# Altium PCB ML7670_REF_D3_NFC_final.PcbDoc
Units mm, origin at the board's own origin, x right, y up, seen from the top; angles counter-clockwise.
Board outline 50 x 7.2 mm, 4 copper layers (Top Layer, Inner Layer 1, Inner Layer 2, Bottom Layer), stack 0.195 mm thick; 35 components, 21 nets, 103 pads, 131 vias.
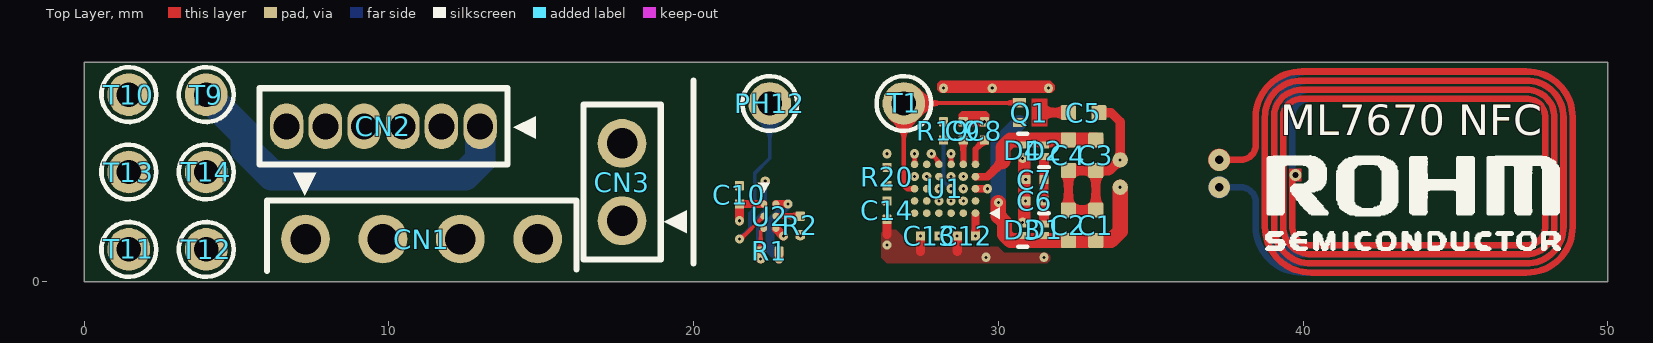
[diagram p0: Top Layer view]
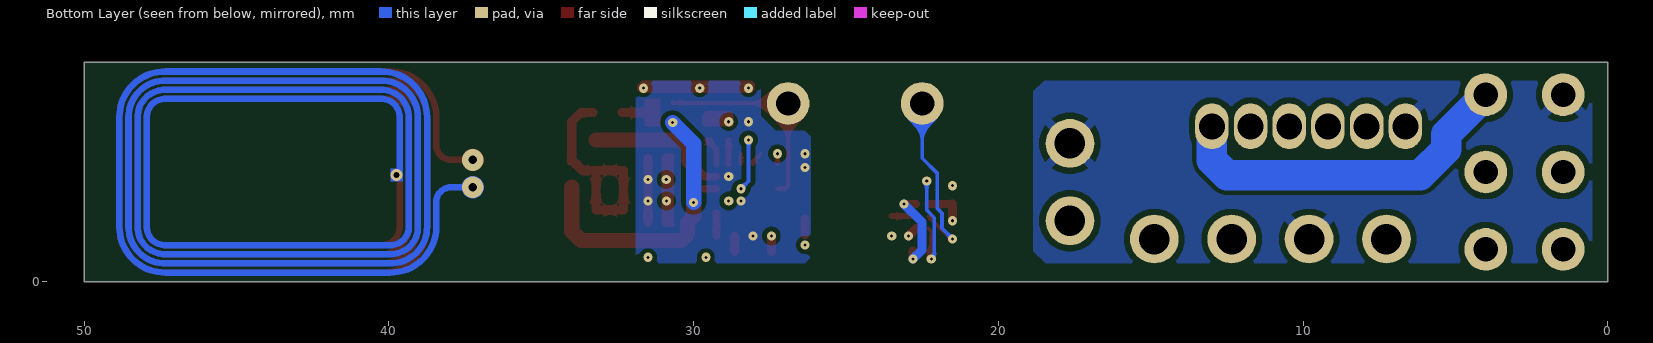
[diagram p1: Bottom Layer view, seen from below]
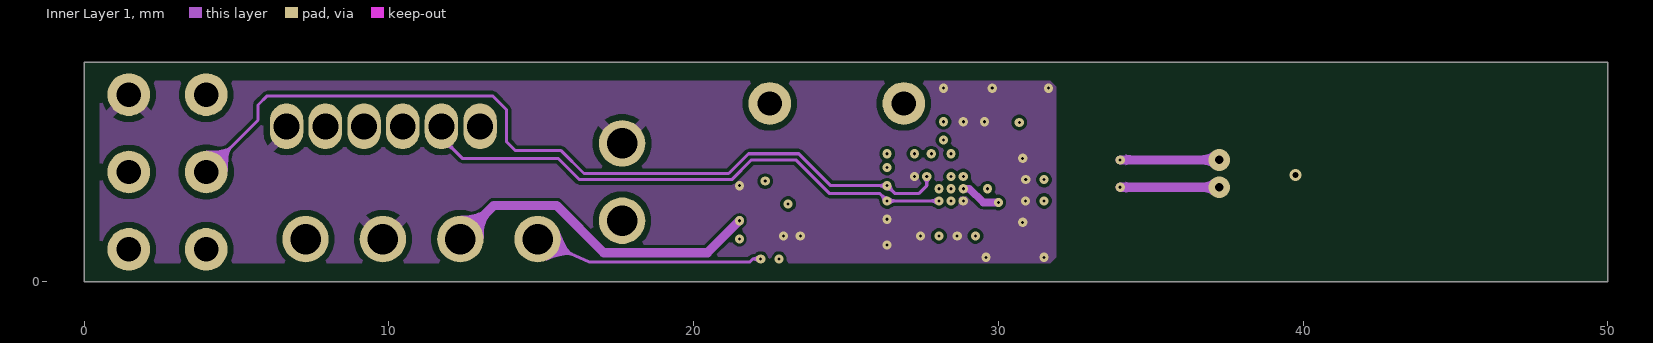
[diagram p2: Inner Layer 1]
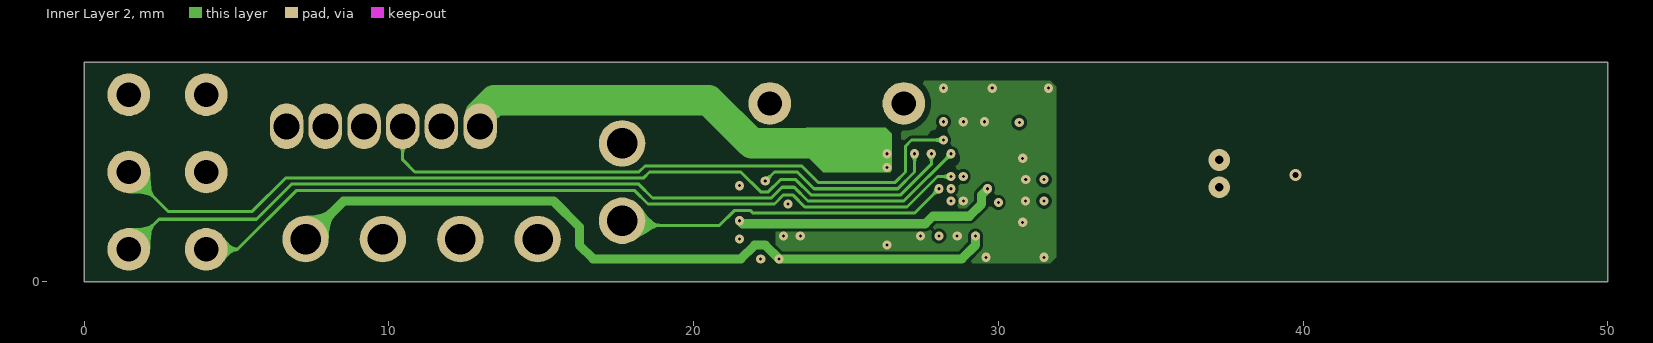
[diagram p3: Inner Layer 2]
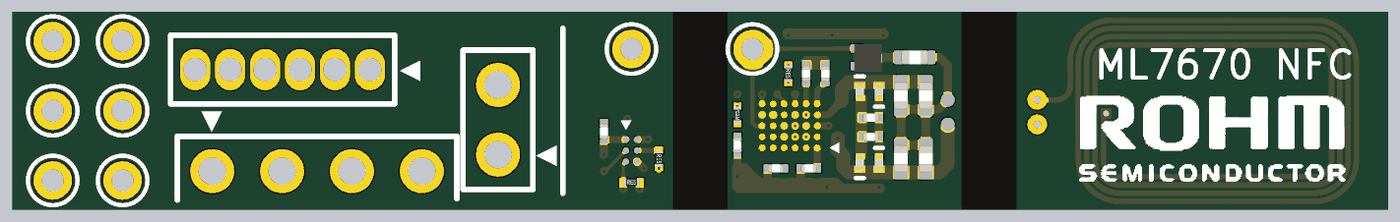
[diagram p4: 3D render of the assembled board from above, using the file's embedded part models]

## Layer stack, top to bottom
Top Solder: solder mask 0.02, Solder Resist, Dk 3.5
Top Layer: signal copper 0.035
Dielectric 1: prepreg 0.005, R-1661, Dk 4.1
Dielectric 2: prepreg 0.025, PP-006, Dk 4.1
Inner Layer 1: signal copper 0.02
Dielectric 3: core 0.025, R-1776KR, Dk 4.8
Inner Layer 2: signal copper 0.02
Dielectric 4: prepreg 0.025, PP-006, Dk 4.1
Dielectric 5: prepreg 0.005, R-1661, Dk 4.1
Bottom Layer: signal copper 0.035
Bottom Solder: solder mask 0.02, Solder Resist, Dk 3.5

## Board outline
0,0 50,0 50,7.2 0,7.2

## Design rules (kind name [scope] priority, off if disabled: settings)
BoardOutlineClearance [All] p1: gap=0.5 ignorepadtopadclearanceinfootprint=FALSE
Clearance Clearance_1 [IsKeepOut] p1: gap=0 ignorepadtopadclearanceinfootprint=TRUE
Clearance Clearance_l2 [OnLayer('Inner Layer 1')] p2: gap=0.1 ignorepadtopadclearanceinfootprint=TRUE except(0: Arc-Text Track-Text SMDPad-Text THPad-Text Via-Text Fill-Text Poly-Text Region-Text; 0.15: Arc-SMDPad Track-SMDPad SMDPad-Via THPad-Via; 0.2: Arc-THPad Arc-Hole Track-THPad Track-Hole SMDPad-SMDPad SMDPad-THPad SMDPad-Fill SMDPad-Poly SMDPad-Region SMDPad-Hole THPad-THPad THPad-Fill THPad-Poly THPad-Region THPad-Hole Via-Hole Fill-Hole Poly-Hole Region-Region Region-Hole; 0.3: Fill-Fill Fill-Poly Fill-Region Poly-Poly)
Clearance Clearance_l3 [OnLayer('Inner Layer 2')] p3: gap=0.2 ignorepadtopadclearanceinfootprint=TRUE except(0: Arc-Text Track-Text SMDPad-Text THPad-Text Via-Text Fill-Text Poly-Text Region-Text; 0.1: Arc-Arc Arc-Track Arc-Via Arc-Fill Arc-Poly Arc-Region Track-Track Track-Via Track-Fill Track-Poly Track-Region Via-Via Via-Fill Via-Poly Via-Region Text-Text Text-Hole; 0.15: Arc-SMDPad Track-SMDPad SMDPad-Via THPad-Via; 0.3: Fill-Fill Fill-Poly Fill-Region Poly-Poly Poly-Region)
Clearance Clearance_bottom [OnLayer('Bottom Layer')] p4: gap=0.2 ignorepadtopadclearanceinfootprint=TRUE except(0.1: Text-Text Text-Hole; 0.13: Arc-Arc Arc-Track Arc-Via Track-Track Track-Via; 0.15: Arc-SMDPad Arc-Fill Arc-Poly Arc-Region Track-SMDPad Track-Fill Track-Poly Track-Region SMDPad-Via THPad-Via Via-Via Via-Fill Via-Poly Via-Region Poly-Region Region-Region; 0.3: Fill-Fill Fill-Poly Fill-Region Poly-Poly)
Clearance Clearance_top [OnLayer('Top Layer')] p5: gap=0.2 ignorepadtopadclearanceinfootprint=TRUE except(0.1: Text-Text Text-Hole; 0.13: Arc-Arc Arc-Track Arc-Via Track-Track Track-Via; 0.15: Arc-SMDPad Arc-Fill Arc-Poly Arc-Region Track-SMDPad Track-Fill Track-Poly Track-Region SMDPad-Via Via-Via Via-Fill Via-Poly Via-Region; 0.3: Fill-Fill Fill-Poly Fill-Region Poly-Poly Poly-Region)
HoleSize [All] p1: absolutevalues=TRUE maxlimit=4 minlimit=0.2 maxpercent=80.000 minpercent=20.000
MinimumSolderMaskSliver [All] p1: minsoldermaskwidth=0.15
PolygonConnect PolygonConnect_1 [All] p1: thpad.connectstyle=Relief thpad.reliefconductorwidth=0.3 thpad.reliefentries=4 thpad.polygonreliefangle="90 Angle" thpad.airgapwidth=0.2 thpad.conductorbypadedge=TRUE thpad.mindistance=0.381 thpad.enablemindistance=FALSE smdpad.connectstyle=NoConnect smdpad.reliefconductorwidth=0.254 smdpad.reliefentries=4 smdpad.polygonreliefangle="90 Angle" smdpad.airgapwidth=0.2 via.connectstyle=Direct via.reliefconductorwidth=0.254 via.reliefentries=4 via.polygonreliefangle="90 Angle" via.airgapwidth=0.254
RoutingVias [All] p1: holewidth=0.6 width=0.3 viastyle="Through Hole" minholewidth=0.5 minwidth=0.2 maxholewidth=1.4 maxwidth=1
SilkToSilkClearance [All] p1: silktosilkclearance=0.1
SilkToSolderMaskClearance [IsPad] p1: minsilkscreentomaskgap=0.1 clearancetoexposedcopper=TRUE
SolderMaskExpansion [All] p1: expansion=0.05 istentingtop=FALSE
SupplyNets "Schematic Supply Nets_6" [InNet('VDD_IO')] p1: voltage=0.000
SupplyNets "Schematic Supply Nets_5" [InNet('CHARGER_VIN')] p2: voltage=0.000
SupplyNets "Schematic Supply Nets_3" [InNet('CHARGER_VOUT')] p3: voltage=0.000
SupplyNets "Schematic Supply Nets_2" [InNet('GND')] p4: voltage=0.000
Width [All] p1: maxlimit=3 minlimit=0.1 preferedwidth=0.12 midlayer1_prefwidth=0.1 midlayer2_prefwidth=0.1 minimp=50.000000 maximp=50.000000 favimp=50.000000
26 further rules are at their usual default settings.

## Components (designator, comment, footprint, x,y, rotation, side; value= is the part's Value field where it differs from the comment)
C1 "Cap" CC1005_02 33.2,1.85 r90 top value=N.M.
C2 "Cap" CC1005_02 32.3,1.85 r90 top value=18pF
C3 "Cap" CC1005_02 33.2,4.15 r90 top value=120pF
C4 "Cap" CC1005_02 32.3,4.15 r90 top value=3.9pF
C5 "Cap" CC1005_02 32.8,5.55 r180 top value=15pF
C6 "Cap" 0603-1_00 31.2,2.65 r180 top value=2.2μF
C7 "Cap" 0603-1_00 31.2,3.35 r180 top value=47pF
C8 "Cap" 0603-1_00 29.55,4.95 r270 top value=0.47uF
C9 "Cap" 0603-1_00 28.85,4.95 r270 top value=2.2uF
C10 "Cap" 0603-1_00 21.5,2.85 r90 top value=1μF
C12 "Cap" 0603-1_00 28.95,1.5 r180 top value=1uF
C13 "Cap" 0603-1_00 27.75,1.5 r180 top value=0.1uF
C14 "Cap" 0603-1_00 26.35,2.35 r270 top value=N.M.
CN1 "CN1" J4P-2.54_01 11.07,1.4 r0 top
CN2 "MHDR1X6" CN6_XB-1-5 12.99,5.1 r180 top value="6-Pin Header"
CN3 "Header 2" JP2-2.54_01 17.65,3.27 r90 top value="2-Pin Header"
D1 "RB532HS-30" SOD-962_12_00 31.5,1.7 r90 top
D2 "RB532HS-30" SOD-962_12_00 31.5,4.3 r270 top
D3 "RB532HS-30" SOD-962_12_00 30.8,1.7 r270 top
D4 "RB532HS-30" SOD-962_12_00 30.8,4.3 r90 top
PH12 "" TH0.8_1.4_00 22.5,5.85 r90 top value="Small Pad"
Q1 "RV8L002SNHZG" DFN1010-3W_GSD 31.1,5.55 r270 top value=-
R1 "2.2kΩ" 0603-1_01 22.5,1 r0 top
R2 "6.6k" 0603-1_01 23.5,1.85 r270 top
R19 "10kΩ" 0603-1_01 28.2,4.95 r270 top
R20 "10kΩ" 0603-1_01 26.35,3.45 r90 top
T1 "" TH0.8_1.4_00 26.9,5.85 r0 top value="Small Pad"
T9 "" TH0.8_1.4_00 4,6.14 r0 top value="Small Pad"
T10 "" TH0.8_1.4_00 1.46,6.14 r0 top value="Small Pad"
T11 "" TH0.8_1.4_00 1.46,1.06 r0 top value="Small Pad"
T12 "" TH0.8_1.4_00 4,1.06 r0 top value="Small Pad"
T13 "" TH0.8_1.4_00 1.46,3.6 r0 top value="Small Pad"
T14 "" TH0.8_1.4_00 4,3.6 r0 top value="Small Pad"
U1 "-" ML7670_WL-CSP30_00 28.25,3.05 r90 top
U2 "BQ25101YFPR" "DSBGA (YFP)" 22.5,2.15 r270 top

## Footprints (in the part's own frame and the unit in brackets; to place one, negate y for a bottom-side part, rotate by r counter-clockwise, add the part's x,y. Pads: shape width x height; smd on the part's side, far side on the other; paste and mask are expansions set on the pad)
0603-1_00 [mm]
  rrect17% 0.3x0.3 smd: 1(-0.3,0) 2(0.3,0)
  body extent -0.3,-0.16 0.3,0.16, height 0.32
0603-1_01 [mm]
  rrect17% 0.3x0.3 smd paste-2539.97: 1(-0.3,0) 2(0.3,0)
  body extent -0.3,-0.15 0.3,0.15, height 0.25
CC1005_02 [mm]
  rrect22% 0.5x0.5 smd: 1(-0.5,0) 2(0.5,0)
  body extent -0.5,-0.26 0.5,0.26, height 0.52
CN6_XB-1-5 [mm] "XB-1-5-6P プリント板ニ段重ね用コンスルー"
  oval 1.1x1.5 hole 0.85 mask-2539.97: 1(0,0) 2(1.27,0) 3(2.54,0) 4(3.81,0) 5(5.08,0) 6(6.35,0)
  silkscreen extent -0.9,-1.25 7.24,1.25
DFN1010-3W_GSD [mm]
  round 0.025 smd: D(0,0.25)
  rect 0.3x0.425 smd: G(-0.325,-0.412) S(0.325,-0.412)
  Top Layer region: -0.15,0.5 -0.15,0.65 0.15,0.65 0.15,0.5 0.45,0.5 0.45,0 -0.45,0 -0.45,0.5
  body extent -0.48,-0.51 0.52,0.51, height 0.41
"DSBGA (YFP)" [mm]
  round 0.23 smd mask+0.05: A1(-0.4,-0.2) A2(-0.4,0.2) B1(0,-0.2) B2(0,0.2) C1(0.4,-0.2) C2(0.4,0.2)
  body extent -0.6,-0.45 0.6,0.45, height 0.5
J4P-2.54_01 [mm]
  round 1.6 / inner round 1.524 / far side round 1.6 hole 1: 1(-3.81,0) 2(-1.27,0) 3(1.27,0) 4(3.81,0)
  silkscreen extent -5.08,-1.05 5.08,1.27
JP2-2.54_01 [mm]
  round 1.6 / inner round 1.524 / far side round 1.6 hole 1: 1(-1.27,0) 2(1.27,0)
  silkscreen extent -2.54,-1.27 2.54,1.27
ML7670_WL-CSP30_00 [mm]
  round 0.25 smd paste-2539.97 mask+0.013: A1(-0.8,-1) A2(-0.8,-0.6) A3(-0.8,-0.2) A4(-0.8,0.2) A5(-0.8,0.6) A6(-0.8,1) B1(-0.4,-1) B2(-0.4,-0.6) B3(-0.4,-0.2) B4(-0.4,0.2) B5(-0.4,0.6) B6(-0.4,1) C1(0,-1) C2(0,-0.6) C3(0,-0.2) C4(0,0.2) C5(0,0.6) C6(0,1) D1(0.4,-1) D2(0.4,-0.6) D3(0.4,-0.2) D4(0.4,0.2) D6(0.4,1) E1(0.8,-1) E2(0.8,-0.6) E3(0.8,-0.2) E4(0.8,0.2) E5(0.8,0.6) E6(0.8,1)
  round 0.275 smd paste-2539.97 mask+0.013: D5(0.4,0.6)
  body extent -1.14,-1.28 1.14,1.28, height 0.41
SOD-962_12_00 [mm]
  rect 0.23x0.31 smd paste+0 mask+0: A(-0.19,0) K(0.19,0)
  body extent -0.3,-0.15 0.3,0.15, height 0.29
TH0.8_1.4_00 [mm]
  round 1.4 hole 0.8 mask+0.05: 1(0,0)
  silkscreen extent -0.9,-0.9 0.9,0.9

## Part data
C1: "Capacitor", Part Number=-
C2: "Capacitor", Part Number=GRM1555C1H180GA01#
C3: "Capacitor", Part Number=GRM1555C2A121GE01#
C4: "Capacitor", Part Number=GRM1555C1H3R9BA01#
C5: "Capacitor", Part Number=GRM1555C2A150GE02#
C6 C9: "Capacitor", Part Number=GRM035R61C225ME01#
C7: "Capacitor", Part Number=GRM0335C1H470FA01#
C8: "Capacitor", Part Number=GRM033R60J474KE90#
C10: "Capacitor", Part Number=GRM033R61C105ME15D
C12: "Capacitor", Part Number=GRM033R61C105ME15#
C13 C14: "Capacitor", Part Number=GRM033R61C104KE18#
CN1: library part CN
CN2: "Header, 6-Pin", Part Number=XB-1-5-6P
CN3: "Header, 2-Pin", Part Number=PH-1x2SG
D1 D2 D3 D4: library part RB532
PH12 T1 T9 T10 T11 T12 T13 T14: library part TP, "TP", Part Number=-
Q1: library part MOSFET-N, "N-Channel MOSFET", Part Number=RV8L002SNHZGG2CR
R1: library part Res3, "Resistor", Part Number=ERJ-1GNJ222C
R2: library part Res3, "Resistor", Part Number=ERJ-1GNJ332C
R19 R20: library part Res3, "Resistor", Part Number=ERJ-1GNJ103C
U1: library part ML7670, "NFC TX, WQFN40"
U2: library part BQ25101

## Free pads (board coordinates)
  round 0.5 smd: 3(34,3.1) 3(34,4)

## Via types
v1: diameter 0.3, hole 0.1, Top Layer to Inner Layer 1, tented both sides, 52 vias
v2: diameter 0.3, hole 0.1, Inner Layer 1 to Inner Layer 2, tented both sides, 43 vias
v3: diameter 0.3, hole 0.1, Inner Layer 2 to Bottom Layer, tented both sides, 33 vias
v4: diameter 0.72, hole 0.28, Top Layer to Bottom Layer, 2 vias
v5: diameter 0.4, hole 0.2, Top Layer to Bottom Layer, 1 vias

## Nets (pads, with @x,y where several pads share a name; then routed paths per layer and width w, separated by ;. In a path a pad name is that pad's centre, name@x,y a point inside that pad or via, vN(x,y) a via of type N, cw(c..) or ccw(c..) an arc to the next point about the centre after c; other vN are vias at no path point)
Charger_LEDCNT: CN1.4 R1.1 U1.E6 U2.C1 | length 17.7
  Top Layer w0.12: R1.1 22.2,1.65 U2.C1 ; U1.E6 v1(27.25,4.2)
  Top Layer w0.3: v3(22.2,0.75) R1.1
  Inner Layer 1 w0.1: CN1.4 16.568,0.65 21.85,0.65 21.95,0.75 v3(22.2,0.75)
  Inner Layer 2 w0.1: v3(22.35,3.3) 22.65,3.6 23.4,3.6 23.95,3.05 26.7,3.05 27.25,3.6 v1(27.25,4.2)
  Bottom Layer w0.12: v3(22.2,0.75) 22.1,0.85 22.1,2.1 22.35,2.35 v3(22.35,3.3)
  other v1: 22.2,0.75 22.35,3.3
  other v2: 22.2,0.75 22.35,3.3 27.25,4.2
  other v3: 27.25,4.2
CHARGER_VIN: C12.1 CN1.1 R1.2 U1.A1 U2.A2 | length 28.1
  Top Layer w0.25: U2.A2 v3(23.1,2.55) ; v2(29.25,1.5) U1.A1
  Top Layer w0.3: v3(22.8,0.75) R1.2
  Inner Layer 2 w0.3: CN1.1 8.51,2.65 15.4,2.65 16.25,1.8 16.25,1.2 16.7,0.75 21.55,0.75 22,1.2 22.35,1.2 v3(22.8,0.75) 28.8,0.75 29.25,1.2 v2(29.25,1.5)
  Bottom Layer w0.3: v3(22.8,0.75) 22.5,1.05 22.5,1.95 v3(23.1,2.55)
  other v1: 22.8,0.75 29.25,1.5 23.1,2.55
  other v2: 22.8,0.75 23.1,2.55
CHARGER_VOUT: C10.1 CN1.3 U1.C1 U2.A1 | length 21.3
  Top Layer w0.25: C10.1 U2.A1 ; U1.C1 v1(29.65,3.05)
  Top Layer w0.3: v2(21.5,2) C10.1
  Inner Layer 1 w0.3: CN1.3 13.44,2.5 15.5,2.5 17.05,0.95 20.45,0.95 v2(21.5,2)
  Inner Layer 2 w0.3: v2(21.5,2) 21.6,1.9 27.6,1.9 27.85,2.15 29.05,2.15 29.45,2.55 29.45,2.85 v1(29.65,3.05)
  other v1: 21.5,2
  other v2: 29.65,3.05
  other v3: 21.5,2
GND: C6.2 C7.2 C8.1 C9.1 C10.2 C12.2 C13.2 C14.2 CN1.2 CN2.6 CN3.2 D3.A D4.A R2.2 T10.1 U1.B2 U1.D6 U2.C2 | length 1.9
  Top Layer w0.3: U2.C2 v1(22.95,1.5) ; 26.35,1.55 v1(26.35,2.05) ; 27.45,1 v1(27.45,1.5) ; 28.65,1 v1(28.65,1.5)
  other v1: 29.6,0.8 31.5,0.8 26.35,1.2 23.5,1.5 30.8,1.95 28.85,2.65 30.894,2.647 21.5,3.15 30.9,3.35 27.25,3.45 30.8,4.05 28.85,5.25 29.55,5.25 28.2,6.35 29.8,6.35 31.65,6.35
  other v2: 29.6,0.8 31.5,0.8 26.35,1.2 22.95,1.5 23.5,1.5 27.45,1.5 28.65,1.5 30.8,1.95 28.85,2.65 30.894,2.647 21.5,3.15 30.9,3.35 30.8,4.05 28.85,5.25 29.55,5.25 28.2,6.35 29.8,6.35 31.65,6.35
  other v3: 29.6,0.8 31.5,0.8 26.35,1.2 22.95,1.5 23.5,1.5 27.45,1.5 28.85,2.65 30.894,2.647 21.5,3.15 30.9,3.35 28.85,5.25 28.2,6.35 29.8,6.35 31.65,6.35
MCSEL0: Q1.G T1.1 U1.C6 | length 6.9
  Top Layer w0.15: U1.C6 27,3.05 26.9,3.15 T1.1 Q1.G@30.687,5.874
NetC1_1: C1.1 C2.1 D1.A D3.K pad.3@34,3.1 Q1.S U1.C2 | length 14.1
  Top Layer w0.5: v1(30,2.6) 30,2.15 30.2,1.95 30.2,1.55 30.4,1.35 C2.1 C1.1 33.7,1.35 34,1.65 v1(34,3.1)
  Inner Layer 1 w0.25: v1(28.85,3.05) 29.05,3.05 29.5,2.6 v1(30,2.6)
  Inner Layer 1 w0.3: v1(34,3.1) v4(37.25,3.1)
  Bottom Layer w0.5: v1(30,2.6) 30,4.537 v1(30.688,5.225)
  other v2: 30,2.6 30.688,5.225
  other v3: 30,2.6 30.688,5.225
NetC1_2: C1.2 C2.2 C3.1 C4.1 C5.1 pad.3@34,4 | length 10.7
  Top Layer w0.3: C5.1 33.7,5.55 34,5.25 v1(34,4) ; pad.3@34,3.95 v1(34,4) ; C3.1 33.65,3.65 v1(34,4) ; C3.1 C4.1 C2.2 C1.2 C3.1
  Inner Layer 1 w0.3: v1(34,4) v4(37.25,4)
NetC3_2: C3.2 C4.2 D2.A D4.K U1.D1 | length 4.7
  Top Layer w0.25: U1.D1 29.65,3.45 30.15,3.95
  Top Layer w0.5: 30.15,3.95 30.15,4.4 30.4,4.65 31.5,4.65 C4.2 C3.2
NetC5_2: C5.2 Q1.D | length 0.9
  Top Layer w0.3: 31.45,5.55 C5.2@32.35,5.55
NetC8_2: C8.2 U1.E1 | length 0.9
  Top Layer w0.2: U1.E1 29.25,4.35 C8.2
NetC9_2: C9.2 U1.E2 | length 0.8
  Top Layer w0.2: U1.E2 C9.2
NetPH12_1: PH12.1 U2.B1 | length 6
  Top Layer w0.12: v2(21.5,1.4) 21.55,1.4 U2.B1
  Bottom Layer w0.12: v2(21.5,1.4) 21.85,1.75 21.85,2.25 22,2.4 22,3.55 22.5,4.05 PH12.1@22.5,5.9
  other v1: 21.5,1.4
  other v3: 21.5,1.4
NetR2_1: R2.1 U2.B2 | length 0.8
  Top Layer w0.2: U2.B2 R2.1
NetR20_1: R20.1 T14.1 U1.D5 | length 27.9
  Inner Layer 1 w0.1: T14.1 5.7,5.3 5.7,5.8 6,6.1 13.4,6.1 13.85,5.65 13.85,4.6 14.15,4.3 15.65,4.3 16.4,3.55 21.15,3.55 21.8,4.2 23.45,4.2 24.5,3.15 v1(26.35,3.15) 26.6,2.9 27.4,2.9 27.65,3.15 v1(27.65,3.45)
NetT11_1: T11.1 U1.E3 | length 29.4
  Top Layer w0.12: U1.E3 v1(28.45,4.2)
  Inner Layer 2 w0.1: T11.1 2.45,2.05 5.65,2.05 6.8,3.2 18.2,3.2 18.65,2.75 22.55,2.75 22.9,3.1 23.3,3.1 23.75,2.65 26.9,2.65 v1(28.45,4.2)
  other v2: 28.45,4.2
NetT12_1: T12.1 U1.D3 | length 26.1
  Inner Layer 2 w0.1: T12.1 5.028,1.06 6.968,3 18.05,3 18.5,2.55 22.65,2.55 22.95,2.85 23.25,2.85 23.65,2.45 27,2.45 28,3.45 v1(28.45,3.45)
  other v2: 28.45,3.45
NetT13_1: T13.1 U1.E4 | length 29.3
  Top Layer w0.12: v1(27.8,4.2) 28.05,3.95 U1.E4
  Inner Layer 2 w0.1: T13.1 2.76,2.3 5.5,2.3 6.6,3.4 18.35,3.4 18.55,3.6 21.55,3.6 22.2,2.95 22.45,2.95 22.85,3.35 23.35,3.35 23.85,2.85 26.8,2.85 27.8,3.85 v1(27.8,4.2)
  other v2: 27.8,4.2
RESET_N: C14.1 CN2.2 U1.B4 | length 18.1
  Inner Layer 1 w0.1: CN2.2 11.72,4.73 12.4,4.05 15.55,4.05 16.25,3.35 21.25,3.35 21.9,4 23.35,4 24.45,2.9 26.1,2.9 v1(26.35,2.65) v1(28.05,2.65)
TEST0: CN2.3 R19.2 U1.C3 | length 22.1
  Inner Layer 2 w0.1: CN2.3 10.45,4 10.85,3.6 18.2,3.6 18.4,3.8 23.55,3.8 24.1,3.25 26.6,3.25 26.95,3.6 26.95,4.45 27.15,4.65 v2(28.2,4.65)
  Bottom Layer w0.12: v2(28.2,4.65) 28.2,3.3 v1(28.45,3.05)
  other v1: 28.2,4.65
  other v2: 28.45,3.05
  other v3: 28.45,3.05 28.2,4.65
TXD: CN3.1 U1.C4 | length 11
  Inner Layer 2 w0.1: CN3.1@17.65,1.85 20.85,1.85 21.33,2.33 21.87,2.33 21.95,2.25 27.25,2.25 v1(28.05,3.05)
  other v2: 28.05,3.05
VDD_IO: C6.1 C7.1 C13.1 CN2.1 D1.K D2.K R19.1 R20.2 T9.1 U1.B3 U1.D2 | length 27.5
  Top Layer w0.3: D1.K@31.5,1.95 v2(31.5,2.65) v2(31.5,3.35) D2.K@31.5,4.05
  Inner Layer 2 w1: CN2.1@13,5.5 13.45,5.95 20.5,5.95 21.9,4.55 25.95,4.55
  Bottom Layer w1: T9.1 5.3,4.84 5.3,4.35 6.15,3.5 12.5,3.5 12.99,3.99 CN2.1
  other v1: 28.05,1.5 28.45,2.65 31.5,2.65 31.5,3.35 28.85,3.45 26.35,3.75 26.35,4.2 28.2,5.25
  other v2: 28.05,1.5 28.45,2.65 28.85,3.45 26.35,3.75 26.35,4.2 28.2,5.25
  other v3: 28.05,1.5 28.45,2.65 31.5,2.65 31.5,3.35 28.85,3.45 26.35,3.75 26.35,4.2 28.2,5.25
pads on no net: CN2.4 CN2.5 U1.A2 U1.A3 U1.A4 U1.A5 U1.A6 U1.B1 U1.B5 U1.B6 U1.C5 U1.D4 U1.E5
copper on no net:
  other v5: 39.75,3.5

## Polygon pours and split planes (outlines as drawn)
VDD_IO on Bottom Layer "GND_L01_P-001" (solid, pour order 0): 31.7,0.6 31.9,0.8 31.9,6.4 31.7,6.6 28,6.6 27.8,6.4 27.8,5.45 27.3,4.95 26.35,4.95 26.15,4.75 26.15,0.8 26.35,0.6
GND on Bottom Layer "GND_L01_P-001" (solid, pour order 3): 0.5,0.85 0.75,0.6 18.45,0.6 18.85,1 18.85,6.25 18.5,6.6 0.75,6.6 0.5,6.35
GND on Inner Layer 2 "GND_L01_P-001" (solid, pour order 4): 26.15,1.9 22.7,1.9 22.7,1.05 23.05,0.7 26.25,0.7 26.35,0.6 31.7,0.6 31.9,0.8 31.9,6.4 31.7,6.6 26.35,6.6 26.15,6.4
GND on Inner Layer 1 "GND_L01_P-001" (solid, pour order 1): 31.7,0.6 31.9,0.8 31.9,6.4 31.7,6.6 0.5,6.6 0.5,0.6
GND on Top Layer "GND_L01_P-001" (solid, pour order 5): 26.25,1.7 26.15,1.6 26.15,0.789 26.339,0.6 31.6,0.6 31.7,0.7 31.7,0.85 31.6,0.95 30.2,0.95 30,1.15 27.2,1.15 27.05,1.3 26.65,1.7

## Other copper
Top Layer:
  region net GND: 30.65,4.2 30.95,4.2 31.05,4.1 31.05,1.9 30.95,1.8 30.65,1.8
  region: 28.7,5.1 29.7,5.1 29.7,5.5 29.6,5.6 28.8,5.6 28.7,5.5
  region net GND: 28.1,6.2 31.75,6.2 31.85,6.3 31.85,6.45 31.7,6.6 28.1,6.6 28,6.5 28,6.3
  region net NetC1_2: 723 vertices and 0 holes, not listed, extent 36.889,0.2 48.95,7
Inner Layer 2:
  region net VDD_IO: 24.25,3.6 23.7,4.15 23.7,5.05 26.3,5.05 26.5,4.85 26.5,3.65 26.45,3.6
Bottom Layer:
  region net NetC1_1: 723 vertices and 0 holes, not listed, extent 36.889,0.2 48.95,7

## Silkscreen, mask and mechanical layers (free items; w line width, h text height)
Top Overlay:
  drawing of 27 lines, arcs and shapes, not listed
  text "ML7670 NFC" at 39.25,4.8 h1
Top Solder:
  region: 24,0 26,0 26,7.2 24,7.2
  region: 34.5,0 36.5,0 36.5,7.2 34.5,7.2
Bottom Solder:
  region: 34.5,0 36.5,0 36.5,7.2 34.5,7.2
  region: 24,0 26,0 26,7.2 24,7.2
Mechanical 1:
  the board outline again, w0.15
Top Component Outline:
  lines w0.1: 20,0.1 20,7.1 ; 25,0 25,7.2 ; 35.5,0 35.5,7.2
  lines w0.15: 30.65,1.55 30.95,1.55 ; 30.65,4.45 30.95,4.45 ; 31.35,1.85 31.65,1.85 ; 31.35,4.15 31.65,4.15
Mechanical 30 (Mech30):
  drawing of 735 lines, arcs and shapes, not listed
Mechanical 31 (Mech31):
  drawing of 724 lines, arcs and shapes, not listed
Mechanical 32 (Mech32):
  lines w0.013: 39.609,3.5 39.619,3.446 ; 39.609,3.5 39.619,3.446 ; 39.609,3.5 39.619,3.554 ; 39.609,3.5 39.619,3.554 ; 39.609,3.5 39.619,3.554 ; 39.609,3.5 39.619,3.446 ; 39.619,3.446 39.65,3.4 ; 39.619,3.446 39.65,3.4 ; 39.619,3.446 39.65,3.4 ; 39.619,3.554 39.65,3.6 ; 39.619,3.554 39.65,3.6 ; 39.619,3.554 39.65,3.6 ; 39.65,3.4 39.696,3.369 ; 39.65,3.4 39.696,3.369 ; 39.65,3.4 39.696,3.369 ; 39.65,3.6 39.696,3.631 ; 39.65,3.6 39.696,3.631 ; 39.65,3.6 39.696,3.631 ; 39.696,3.369 39.75,3.359 ; 39.696,3.369 39.75,3.359 ; 39.696,3.369 39.75,3.359 ; 39.696,3.631 39.75,3.641 ; 39.696,3.631 39.75,3.641 ; 39.696,3.631 39.75,3.641 ; 39.75,3.359 39.804,3.369 ; 39.75,3.359 39.804,3.369 ; 39.75,3.359 39.804,3.369 ; 39.75,3.641 39.804,3.631 ; 39.75,3.641 39.804,3.631 ; 39.75,3.641 39.804,3.631 ; 39.804,3.369 39.85,3.4 ; 39.804,3.369 39.85,3.4 ; 39.804,3.369 39.85,3.4 ; 39.804,3.631 39.85,3.6 ; 39.804,3.631 39.85,3.6 ; 39.804,3.631 39.85,3.6 ; 39.85,3.4 39.881,3.446 ; 39.85,3.4 39.881,3.446 ; 39.85,3.4 39.881,3.446 ; 39.85,3.6 39.881,3.554 ; 39.85,3.6 39.881,3.554 ; 39.85,3.6 39.881,3.554 ; 39.881,3.446 39.891,3.5 ; 39.881,3.446 39.891,3.5 ; 39.881,3.446 39.891,3.5 ; 39.881,3.554 39.891,3.5 ; 39.881,3.554 39.891,3.5 ; 39.881,3.554 39.891,3.5

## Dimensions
0,-0.229 to 50,-0.3 on Mechanical 10
35.5,-0.2 to 50,-0.3 on Mechanical 10
25,-0.25 to 35.5,-0.2 on Mechanical 10
20,0.1 to 25,0.1 on Mechanical 10
24,7.35 to 26,7.3 on Mechanical 10
0,0 to 20,0.1 on Mechanical 10
0,0 to 0,7.2 on Mechanical 10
